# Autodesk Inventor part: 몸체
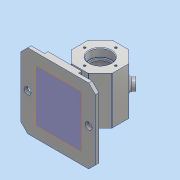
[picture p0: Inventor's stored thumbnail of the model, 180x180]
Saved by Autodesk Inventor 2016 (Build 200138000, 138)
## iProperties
Created: 2018-06
Part Number: 몸체
Material: 알루미늄 6061
Document SubType Name: Modeling
Designer: 605-11
Density: 2.7 g/cm^3
Appearance: 알루미늄 - 평지
Mass: 551.997 g
Surface Area: 601.935 cm^2
Volume: 204.443 cm^3
Author: 605-11
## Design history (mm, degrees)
sketch "스케치1"
  geometry: L1 (30, -12.426)-(12.426, -30); L2 (12.426, -30)-(-12.426, -30); L3 (-12.426, -30)-(-30, -12.426); L4 (-30, -12.426)-(-30, 12.426); L5 (-30, 12.426)-(-12.426, 30); L6 (-12.426, 30)-(12.426, 30); L7 (12.426, 30)-(30, 12.426); L8 (30, 12.426)-(30, -12.426); L9 (0, 0)-(-12.426, 30); L10 (0, 0)-(0, 30); L11 (0, 0)-(12.426, 30); 1 further point
  constraints: 22 end point, 2 point on line, 1 coincident, 1 midpoint, 1 vertical, 1 vertical alignment, 17 other
  dimensions: "d0" = 60 distance between parallel lines of L8 L4; "d1" = 22.5 deg angle of L10 L9; "d2" = 45 deg angle of L11 L9
extrude "돌출1" new body sketch "스케치1" stored distance "d3" = 70; taper "d4" = 0 deg
sketch "스케치2"
  geometry: L1 (0, 35)-(16, 35); L2 (16, 35)-(16, 23.3); L3 (15.7, 23)-(0, 23); L4 (0, 23)-(0, 35); L5 (0, 23)-(14, 23); L6 (14, 23)-(14, 20); L7 (14, 20)-(0, 20); L8 (0, 20)-(0, 23); L9 (0, 20)-(22, 20); L10 (25, 17)-(25, -17); L11 (22, -20)-(0, -20); L12 (0, -20)-(0, 20); L13 (0, -20)-(14, -20); L14 (14, -20)-(14, -23); L15 (14, -23)-(0, -23); L16 (0, -23)-(0, -20); L17 (0, -23)-(15.7, -23); L18 (16, -23.3)-(16, -35); L19 (16, -35)-(0, -35); L20 (0, -35)-(0, -23); L21 (12.426, 35)-(-12.426, 35) reference; A1 r 0.3 centre (15.7, 23.3) between (15.7, 23) and (16, 23.3); A2 r 0.3 centre (15.7, -23.3) between (16, -23.3) and (15.7, -23); A3 r 3 centre (22, -17) between (22, -20) and (25, -17); A4 r 3 centre (22, 17) between (25, 17) and (22, 20); 6 further points
  constraints: 40 end point, 10 parallel, 8 point on circle, 8 point on line, 8 tangent, 5 horizontal, 5 perpendicular, 4 centre point, 2 equal radius, 1 coincident, 1 midpoint
  dimensions: "d5" = 12 distance of L1.end point (16, 23); "d6" = 16 distance of L1.start L1.end; "d7" = 3 distance of L5.end L6.end; "d8" = 14 distance of L3.end L5.end; "d9" = 40 distance of point (25, 20) point (25, -20); "d10" = 25 distance of L7.end point (25, 20); "d11" = 3 distance of L13.end L14.end; "d12" = 14 distance of L11.end L13.end; "d13" = 12 distance of point (16, -23) L18.end; "d14" = 16 distance of L15.end point (16, -23); "d15" = 0.3 radius of A1; "d16" = 3 radius of A3
revolve "회전1" sketch "스케치2" stored, may be unused: angle "d17" = 90 deg
chamfer "모따기1" distance "d18" = 1; stored, may be unused: second distance "d19" = 2, angle "d20" = 45 deg
sketch "스케치3"
  geometry: L1 (-24.853, 70)-(0, 70) reference; C1 r 8 at (-12.426, 35); 2 further points
  constraints: 1 centre point, 1 midpoint, 1 vertical alignment
  dimensions: "d21" = 35 distance from line of L1 C1.centre; "d22" = 16 diameter of C1
extrude "돌출2" join sketch "스케치3" distance "d23" = 7; taper "d24" = 0 deg
fillet "모깎기1" dims "d25" = 3
sketch "스케치4"
  geometry: C1 r 4 at (0, 0); 1 further point
  constraints: 1 centre point, 1 coincident
  dimensions: "d26" = 8 diameter of C1
extrude "돌출3" cut sketch "스케치4" stored distance "d27" = 7; taper "d28" = 0 deg; dims "d5" = 12, "d6" = 16, "d7" = 3, "d8" = 14, "d9" = 40, "d10" = 25, "d11" = 3, "d12" = 14, "d13" = 12, "d14" = 16, "d15" = 0.3, "d16" = 3, "d61" = 55, "d62" = 38, "d63" = 55, "d64" = 5
chamfer "모따기2" distance "d29" = 1; stored, may be unused: second distance "d30" = 2, angle "d31" = 45 deg
sketch "스케치5" dims "d32" = 46
  geometry: 3 further points
  constraints: 2 vertical alignment, 1 coincident, 2 other
hole "구멍1" sketch "스케치5" at (0, 23) diameter "d33" = 3.242; stored, may be unused: countersink angle "d37" = 90 deg, drill point angle "d39" = 118 deg; dims "d34" = 8, "d35" = 4, "d36" = 2, "d38" = 10
fillet "모깎기2" dims "d43" = 1
node "작업 평면1"
sketch "스케치6"
  geometry: L1 (12.012, -35)-(-12.012, -35) reference; L2 (30, -35)-(30, 35) reference; L3 (-30, 35)-(-30, -35) reference; L4 (-12.012, 35)-(12.012, 35) reference; L5 (45, -55)-(-45, -55); L6 (-55, -45)-(-55, 45); L7 (-45, 55)-(45, 55); L8 (55, 45)-(55, -45); L9 (55, -55)-(-55, 55); L10 (-55, -55)-(55, 55); L11 (55, -45)-(45, -55); L12 (55, 45)-(45, 55); L13 (-45, 55)-(-55, 45); L14 (-55, -45)-(-45, -55); 1 further point
  constraints: 20 end point, 8 point on line, 2 midpoint, 2 parallel, 1 horizontal, 1 perpendicular
  dimensions: "d45" = 110 distance of L9.start L10.start; "d46" = 110 distance of L10.start L9.end; "d47" = 10 distance of L8.end L9.start; "d48" = 10 distance of L5.start L9.start (= d47); "d49" = 10 distance of L8.start L10.end (= d47); "d50" = 10 distance of L7.end L10.end (= d49); "d51" = 10 distance of L7.start L9.end (= d47); "d52" = 10 distance of L6.end L9.end (= d51); "d53" = 10 distance of L6.start L10.start (= d47); "d54" = 10 distance of L5.end L10.start (= d53)
extrude "돌출4" join sketch "스케치6" distance "d55" = 5; taper "d56" = 0 deg
sketch "스케치7"
  geometry: L1 (-25, 55)-(25, 55); L2 (25, 55)-(25, -55); L3 (25, -55)-(-25, -55); L4 (-25, -55)-(-25, 55); L5 (-25, 55)-(25, -55); L6 (25, 55)-(-25, -55); L7 (55, 45)-(55, -45) reference; 1 further point
  constraints: 12 end point, 2 midpoint, 2 parallel, 1 horizontal, 1 perpendicular
  dimensions: "d57" = 110 distance of L1.end L2.end; "d58" = 30 distance between parallel lines of L7 L2
extrude "돌출5" join sketch "스케치7" distance "d59" = 5; taper "d60" = 0 deg
sketch "스케치8"
  geometry: L1 (0, 19)-(0, -19); L2 (-5, 19)-(-5, -19); L3 (5, -19)-(5, 19); L4 (-55, 45)-(-55, -45) reference; L5 (45, -55)-(-45, -55) reference; A1 r 5 centre (0, 19) between (5, 19) and (-5, 19); A2 r 5 centre (0, -19) between (-5, -19) and (5, -19); 2 further points
  constraints: 8 end point, 4 point on circle, 4 tangent, 2 centre point, 1 midpoint, 1 parallel, 1 vertical
  dimensions: "d61" = 55 distance from line of L4 point (0, 0); "d62" = 38 distance of L1.start L1.end; "d63" = 55 distance from line of L5 point (0, 0); "d64" = 5 radius of A1
extrude "돌출6" join sketch "스케치8" stored distance "d65" = 5; taper "d66" = 0 deg
fillet "모깎기3" dims "d67" = 2
sketch "스케치9"
  geometry: L1 (-55, -45)-(-55, 45) reference; C1 r 5 at (-45, 0); 1 further point
  constraints: 1 centre point, 1 horizontal alignment
  dimensions: "d70" = 10 distance from line of L1 C1.centre; "d71" = 10 diameter of C1
extrude "돌출7" cut sketch "스케치9" stored distance "d72" = 5; taper "d73" = 0 deg
node "작업 평면2"
sketch "스케치10"
  geometry: L1 (-12.012, 35)-(12.012, 35) reference; L2 (29.707, 35)-(29.707, -35) reference; 2 further points
  constraints: 1 coincident, 1 other
  dimensions: "d78" = 30 distance from line of L2 point (-0.293, 0); "d79" = 35 distance from line of L1 point (-0.293, 0)
feature "엠보싱1" sketch "스케치10" dims "d0" = 60, "d1" = 22.5 deg, "d2" = 45 deg, "d5" = 12, "d6" = 16, "d7" = 3, "d8" = 14, "d9" = 40, "d10" = 25, "d11" = 3, "d12" = 14, "d13" = 12, "d14" = 16, "d15" = 0.3, "d16" = 3, "d76" = 0.5, "d77" = 0
node "솔리드1"
pattern_circular "원형 패턴1" dims angle "d41" = 360 deg
mirror "대칭1"
mirror "대칭2"
other parameters: "d44" = -62, "d74" = 52.25
